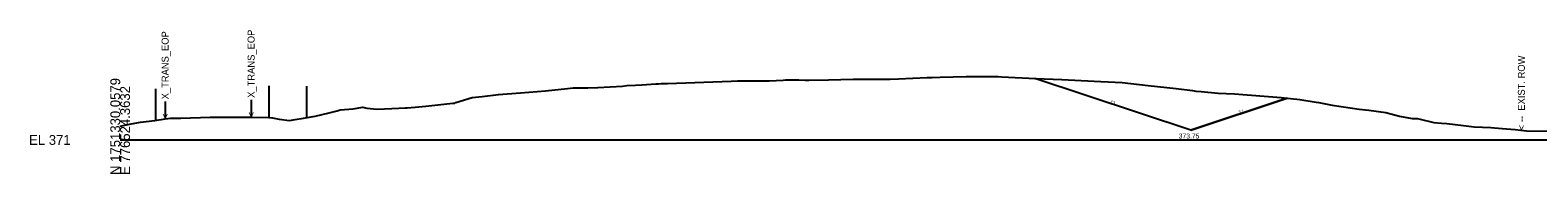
# Model space of a CAD drawing. Extents: x 776426 to 854588, y 1736205 to 1756790.
# Drawn here: x 805845.1 to 806275.5, y 1740705.1 to 1740746.1 of the extents above; entities that cross this region are included whole.
import ezdxf

# ---------------------------------------------------------------- set-up
doc = ezdxf.new("R2010")
doc.units = 0
for name, color, linetype in [('DTM CONTOURS_MAJOR_TX', 7, 'Continuous'), ('DTM_X_FLOW_ARROWS', 7, 'Continuous'), ('TRANS_EOP_PAVED', 7, 'Continuous'), ('TRANS_UNPAVED_SHOULDERS', 7, 'Continuous'), ('X_TRANS_EOP', 7, 'Continuous'), ('XS_M_SHAPES_EARTHWORK', 7, 'Continuous'), ('XS_P_FINISHED_GRADE', 7, 'Continuous'), ('XS_P_TX_DCH', 7, 'Continuous'), ('XS_P_TX_FS_BS', 7, 'Continuous'), ('XS_X_PAVEMENT', 7, 'Continuous'), ('XS_X_ROW', 7, 'Continuous')]:
    doc.layers.add(name, color=color, linetype=linetype)

msp = doc.modelspace()

# ---------------------------------------------------------------- linework, layer by layer
at = {"layer": 'DTM CONTOURS_MAJOR_TX'}
msp.add_line((805870.79, 1740714.76), (806370.79, 1740714.76), dxfattribs=at)
at = {"layer": 'DTM_X_FLOW_ARROWS'}
msp.add_lwpolyline([(805870.79, 1740718.7), (805873.89, 1740719.33), (805876.6, 1740719.87), (805880.66, 1740720.34), (805883.62, 1740720.78), (805884.43, 1740720.88), (805885.07, 1740720.96), (805888.14, 1740721.01), (805896.44, 1740721.26), (805903.51, 1740721.26), (805908.17, 1740721.23), (805913.23, 1740721.19), (805914.31, 1740721.08), (805916.19, 1740720.69), (805919.11, 1740720.3), (805920.71, 1740720.59), (805923.11, 1740721.02), (805926.5, 1740721.54), (805930.48, 1740722.55), (805932.71, 1740723.12), (805933.58, 1740723.32), (805937.27, 1740723.69), (805940.04, 1740724.09), (805941.23, 1740723.88), (805943.08, 1740723.61), (805944.15, 1740723.6), (805948.39, 1740723.79), (805950.35, 1740723.86), (805952.18, 1740723.94), (805952.74, 1740723.98), (805955.01, 1740724.11), (805958.06, 1740724.42), (805965.74, 1740725.26), (805966.29, 1740725.31), (805966.6, 1740725.44), (805971.28, 1740726.84), (805974.15, 1740727.14), (805978.82, 1740727.76), (805985.03, 1740728.18), (805992.23, 1740728.75), (805998.53, 1740729.48), (806000.12, 1740729.63), (806001.98, 1740729.64), (806004.31, 1740729.68), (806007.19, 1740729.75), (806014.19, 1740730.13), (806015.43, 1740730.27), (806017.94, 1740730.44), (806019.67, 1740730.5), (806023.73, 1740730.76), (806024.48, 1740730.82), (806025.22, 1740730.85), (806026.05, 1740730.89), (806027.08, 1740730.93), (806045.17, 1740731.55), (806047.04, 1740731.62), (806048.77, 1740731.63), (806054.34, 1740731.63), (806056.1, 1740731.67), (806060.1, 1740731.86), (806060.75, 1740731.89), (806062.12, 1740731.94), (806064.48, 1740731.9), (806066.34, 1740731.86), (806067.37, 1740731.86), (806073.01, 1740731.92), (806080.08, 1740732.08), (806090.64, 1740732.15), (806092.96, 1740732.21), (806101.2, 1740732.57), (806102.63, 1740732.61), (806104.84, 1740732.67), (806112.33, 1740732.9), (806115.77, 1740732.87), (806119.93, 1740732.86), (806121.41, 1740732.85), (806122.47, 1740732.77), (806132.11, 1740732.35), (806139.62, 1740732.04), (806148.86, 1740731.55), (806150.7, 1740731.48), (806152.82, 1740731.34), (806156.82, 1740731.17), (806164.26, 1740730.32), (806172.25, 1740729.42), (806176.9, 1740728.86), (806177.9, 1740728.69), (806179.36, 1740728.57), (806184.2, 1740728.11), (806188.87, 1740727.95), (806202.25, 1740726.84), (806207.55, 1740726.33), (806212.25, 1740725.58), (806212.96, 1740725.46), (806216.8, 1740724.69), (806224.46, 1740723.53), (806227.21, 1740723.23), (806232.06, 1740722.56), (806235.96, 1740721.58), (806239.6, 1740720.84), (806241.03, 1740720.85), (806241.88, 1740720.66), (806245.79, 1740719.73), (806247.94, 1740719.59), (806249.46, 1740719.44), (806254.3, 1740718.85), (806257.35, 1740718.55), (806262.05, 1740718.29), (806265.31, 1740718.05), (806268.97, 1740717.74), (806272.28, 1740717.39), (806284.14, 1740717.13)], dxfattribs=at)
at = {"layer": 'TRANS_EOP_PAVED'}
for p, q in [((805880.87, 1740729.37), (805880.87, 1740720.37)), ((805880.87, 1740729.37), (805880.87, 1740720.37)), ((805913.25, 1740730.18), (805913.25, 1740721.18)), ((805913.25, 1740730.18), (805913.25, 1740721.18))]:
    msp.add_line(p, q, dxfattribs=at)
at = {"layer": 'TRANS_UNPAVED_SHOULDERS'}
msp.add_line((805923.94, 1740730.15), (805923.94, 1740721.15), dxfattribs=at)
msp.add_line((805923.94, 1740730.15), (805923.94, 1740721.15), dxfattribs=at)
at = {"layer": 'X_TRANS_EOP'}
for p, q in [((805883.62, 1740725.78), (805883.62, 1740720.78)), ((805883.62, 1740725.78), (805883.62, 1740720.78)), ((805908.17, 1740726.23), (805908.17, 1740721.23)), ((805908.17, 1740726.23), (805908.17, 1740721.23))]:
    msp.add_line(p, q, dxfattribs=at)
at = {"layer": 'XS_M_SHAPES_EARTHWORK'}
msp.add_lwpolyline([(806172.25, 1740729.42), (806176.9, 1740728.86), (806177.9, 1740728.69), (806179.36, 1740728.57), (806184.2, 1740728.11), (806188.87, 1740727.95), (806202.25, 1740726.84), (806203.93, 1740726.68), (806176.43, 1740717.51), (806131.88, 1740732.36), (806132.11, 1740732.35), (806139.62, 1740732.04), (806148.86, 1740731.55), (806150.7, 1740731.48), (806152.82, 1740731.34), (806156.82, 1740731.17), (806164.26, 1740730.32)], close=True, dxfattribs=at)
at = {"layer": 'XS_P_FINISHED_GRADE'}
for q in [(806131.88, 1740732.36), (806203.93, 1740726.68)]:
    msp.add_line((806176.43, 1740717.51), q, dxfattribs=at)

# ---------------------------------------------------------------- texts
at = {"layer": 'DTM CONTOURS_MAJOR_TX'}
for s, p in [('N 1751330.0579', (805870.79, 1740704.76)), ('E 776524.3632', (805873.59, 1740704.76))]:
    msp.add_text(s, height=2.8, rotation=90, dxfattribs=at).set_placement(p)
msp.add_text('EL 371', height=2.8, dxfattribs=at).set_placement((805844.79, 1740713.36))
at = {"layer": 'XS_P_TX_DCH'}
msp.add_text('373.75', height=1.4, dxfattribs=at).set_placement((806172.96, 1740715.18))
at = {"layer": 'XS_P_TX_FS_BS'}
for rotation, p in [(341.5651, (806153.33, 1740725.43)), (18.4349, (806190.18, 1740722.31))]:
    msp.add_text('3:1', height=0.8, rotation=rotation, dxfattribs=at).set_placement(p)
at = {"layer": 'XS_X_PAVEMENT'}
for p in [(805884.62, 1740720.78), (805909.17, 1740721.23)]:
    msp.add_text('< --  X_TRANS_EOP', height=2, rotation=90, dxfattribs=at).set_placement(p)
at = {"layer": 'XS_X_ROW'}
msp.add_text('< --  EXIST. ROW', height=2, rotation=90, dxfattribs=at).set_placement((806271.78, 1740717.55))

doc.saveas('drawing.dxf')
